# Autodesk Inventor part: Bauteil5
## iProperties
Created: 2005-04
Part Number: Bauteil5
Cost Center: 0 kg
Checked By: Schilling
Material: Stahl (hohe Festigk., niedr. Legier.)
Document SubType Name: Modeling
Designer: Nützel
Authority: 268,08 mm^3
Manufacturer: Standard
Standards Organization: Custom
SaveDate: 2005-04-24
SaveTime: 14:10
TotalMass: 0 kg
TotalVolume: 268,08 mm^3
Author: Nützel
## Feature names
1. Drehung1 [Revolution]
